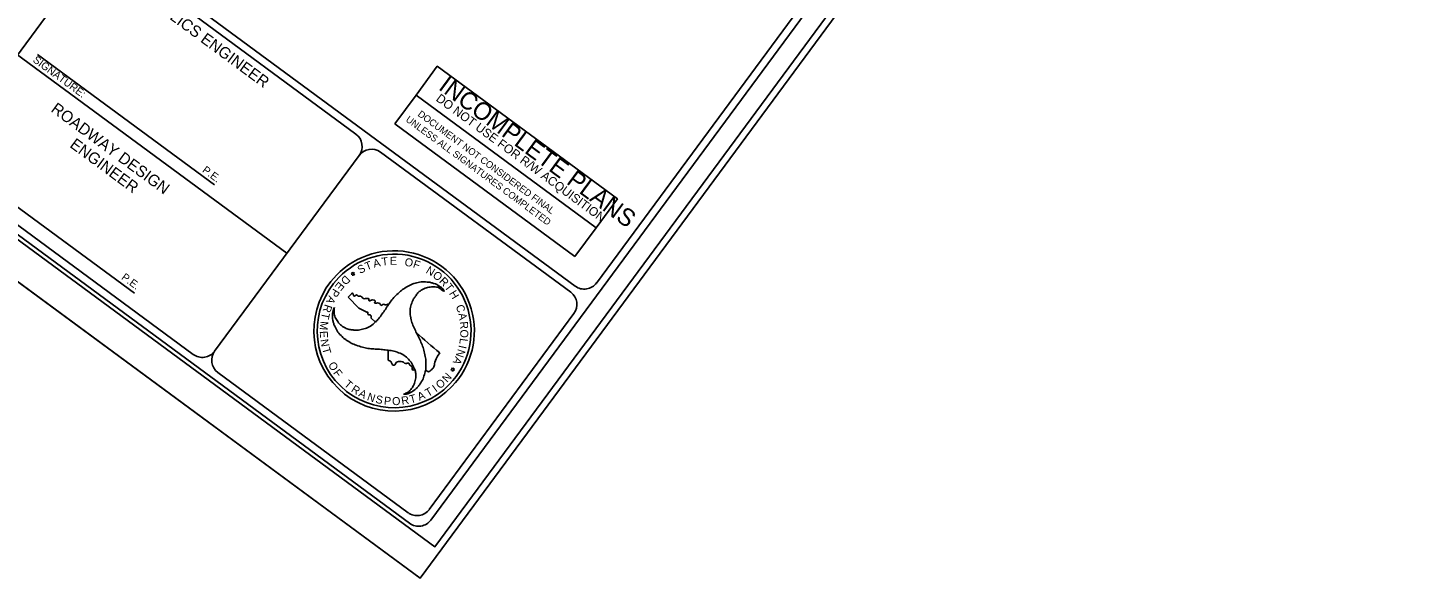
# Model space of a CAD drawing. Extents: x 945666 to 965748, y 644452 to 663300.
# Drawn here: x 956642 to 965748, y 644452 to 648072 of the extents above; entities that cross this region are included whole.
import ezdxf

# ---------------------------------------------------------------- set-up
doc = ezdxf.new("R2010")
doc.units = 0
for name, color, linetype in [('Sheet Cutting Line CELL', 7, 'Continuous'), ('Sheet Plot Border Inside CELL', 7, 'Continuous'), ('Sheet Plot Border Outside CELL', 7, 'Continuous'), ('Sheet Sticker Exception Certification CELL', 7, 'Continuous'), ('Sheet Sticker Incomplete CELL', 7, 'Continuous'), ('Sheet Title CELL', 7, 'Continuous')]:
    doc.layers.add(name, color=color, linetype=linetype)

# ---------------------------------------------------------------- blocks, each defined once
blk = doc.blocks.new('STICKER INCOMPLETE PLANS')
at = {"layer": 'Sheet Sticker Incomplete CELL'}
blk.add_lwpolyline([(0, -0.47), (0, 0), (2.94, 0), (2.94, -0.47)], close=True, dxfattribs=at)
for s, height, p in [('INCOMPLETE PLANS', 0.2304, (0.179, -0.236)), ('DO NOT USE FOR R/W ACQUISITION', 0.1152, (0.244, -0.375))]:
    blk.add_text(s, height=height, dxfattribs=at).set_placement(p)

msp = doc.modelspace()

# ---------------------------------------------------------------- linework, layer by layer
at = {"layer": 'Sheet Cutting Line CELL'}
msp.add_line((945666.1, 654447.6), (959218.9, 644452.2), dxfattribs=at)
at = {"layer": 'Sheet Plot Border Inside CELL'}
msp.add_lwpolyline([(945903.9, 654551), (959315.9, 644659.5), (965578.4, 653150.9), (952166.4, 663042.4)], close=True, dxfattribs=at)
at = {"layer": 'Sheet Plot Border Outside CELL'}
msp.add_lwpolyline([(965747.9, 653304.9), (952195, 663300.2), (945666.1, 654447.6), (959218.9, 644452.2)], close=True, dxfattribs=at)
at = {"layer": 'Sheet Sticker Exception Certification CELL'}
for p, q in [((959052.4, 647440.2), (959191.9, 647629.3)), ((959191.9, 647629.3), (960374.9, 646756.8)), ((960235.4, 646567.7), (959052.4, 647440.2)), ((960374.9, 646756.7), (960235.4, 646567.6))]:
    msp.add_line(p, q, dxfattribs=at)
at = {"layer": 'Sheet Title CELL'}
for p, q in [((948809.3, 654800.8), (960237.5, 646372.5)), ((956100.2, 647249.1), (957049.9, 648536.8)), ((957189.8, 648558), (958797.6, 647372.3)), ((956568.1, 647898.6), (958344, 646588.8)), ((956707.1, 647895.2), (957868.1, 647039)), ((958958.5, 647253.6), (960207.8, 646332.2)), ((956203.7, 647166.2), (957342.4, 646326.2)), ((957869, 645944.8), (958818.7, 647232.5)), ((958765.6, 646451.1), (958773.6, 646455.6)), ((958774.5, 646450.2), (958765.6, 646451.1)), ((958773.6, 646455.6), (958772.1, 646464.6)), ((958772.1, 646464.6), (958778.7, 646458.2)), ((958776.1, 646441), (958774.5, 646450.2)), ((958780.1, 646449.3), (958776.1, 646441)), ((958778.7, 646458.2), (958786.4, 646462.5)), ((958789.3, 646448), (958780.1, 646449.3)), ((958786.4, 646462.5), (958782.8, 646454.3)), ((958782.8, 646454.3), (958789.3, 646448)), ((959378.3, 646340.1), (959376.9, 646339.9)), ((959378.3, 646340.1), (959376.9, 646339.9)), ((958746.4, 646300.7), (958769.2, 646322.8)), ((958815.7, 646228.6), (958746.4, 646300.7)), ((958868.7, 646200.9), (958815.7, 646228.6)), ((958925.5, 646136.3), (958895.8, 646165.6)), ((959194, 646068), (959194, 646068)), ((959008.3, 645886.3), (959009.8, 645951.5)), ((959009.8, 645951.5), (959009.8, 645951.5)), ((959429.4, 645826.9), (959421.4, 645822.5)), ((959421.4, 645822.5), (959430.1, 645821.4)), ((959434.2, 645829.6), (959427.7, 645835.9)), ((959427.7, 645835.9), (959429.4, 645826.9)), ((959430.1, 645821.4), (959431.7, 645812.5)), ((959431.7, 645812.5), (959435.9, 645820.6)), ((959442.1, 645833.8), (959434.2, 645829.6)), ((959435.9, 645820.6), (959445.1, 645819.6)), ((959438.5, 645825.5), (959442.1, 645833.8)), ((959445.1, 645819.6), (959438.5, 645825.5)), ((959427.4, 645712.4), (959427.4, 645712.4))]:
    msp.add_line(p, q, dxfattribs=at)
for points in [[(947238.9, 653598.1), (959149.9, 644813.6)], [(959289.8, 644834.8), (965403.3, 653124.1)], [(960377.3, 646393.5), (965333.4, 653113.7)], [(956121.4, 647109.4), (957729.2, 645923.6)], [(959279.3, 644904.7), (960228.9, 646192.4)], [(957890.2, 645804.9), (959139.4, 644883.6)]]:
    msp.add_lwpolyline(points, dxfattribs=at)
for centre, radius, start, end in [((958738.2, 647291.8), 100, 323.59084, 53.59084), ((958899.2, 647173.1), 100, 53.59084, 143.59084), ((959048.1, 646078.4), 527.2, 316.01198, 136.01198), ((959048.1, 646078.4), 505.2, 316.01198, 136.01198), ((959048.1, 646078.4), 527.2, 136.01198, 316.01198), ((959048.1, 646078.4), 505.2, 136.01198, 316.01198), ((960297.1, 646453.3), 100, 233.59084, 323.59084), ((961085, 648105), 2779.4, 221.69047, 221.79006), ((960148.8, 646252.1), 100, 323.59084, 53.59084), ((961085, 648105), 2779.4, 227.12952, 231.33553), ((957788.9, 646004.6), 100, 233.59084, 323.59084), ((957949.9, 645885.9), 100, 143.59084, 233.59084), ((959199.1, 644964.4), 100, 233.59084, 323.59084), ((959209.6, 644894.5), 100, 233.59084, 323.59084)]:
    msp.add_arc(centre, radius, start, end, dxfattribs=at)
for points in [[(959376.9, 646339.9), (959370.5, 646350.4), (959344.3, 646373.7), (959310.8, 646390.3), (959307.3, 646391.2), (959288, 646396.8), (959264.7, 646399.8), (959225.3, 646400.2), (959186.5, 646391.5), (959170.3, 646387.3), (959153.5, 646379.2), (959119.3, 646360.6), (959089.9, 646338.9), (959059, 646310.3), (959033.9, 646283.4), (959012.1, 646252), (958990.5, 646220.2), (958968.8, 646189.8), (958946.1, 646158.9), (958920.1, 646131.7), (958917.7, 646129.5), (958885, 646105.3), (958848.9, 646091.2), (958813.3, 646084.5), (958795, 646083.3), (958772.7, 646085.7), (958760, 646086.9), (958734.3, 646094.8), (958702.5, 646113.7), (958678.5, 646139.7), (958661.6, 646167.2), (958654, 646199), (958656, 646232.3)], [(959110.1, 645661.7), (959121.8, 645662.1), (959155.3, 645673), (959186.4, 645693.8), (959189.2, 645696), (959203.5, 645710.3), (959217.9, 645729.1), (959238.2, 645762.8), (959249.6, 645800.9), (959254.4, 645816.9), (959255.7, 645835.8), (959256.7, 645874.6), (959252.7, 645910.8), (959243.2, 645951.7), (959232.2, 645986.9), (959216.2, 646021.8), (959199.4, 646056.2), (959184.2, 646089.9), (959168.4, 646125.5), (959158, 646161.4), (959157.5, 646164.7), (959152.6, 646205.5), (959158.7, 646243.7), (959170.3, 646277.8), (959178.8, 646293.8), (959192.1, 646312), (959199.3, 646322.9), (959219.1, 646340.7), (959251.6, 646359), (959285.7, 646366.7), (959317.9, 646367.5), (959349.4, 646358), (959376.9, 646339.9), (959378.3, 646340.1)], [(958769.2, 646322.8), (958770.5, 646325.7), (958776.7, 646324.5), (958783.1, 646309.8), (958793, 646309.2), (958797.2, 646314), (958805.9, 646314.5), (958811.8, 646306), (958826.6, 646308), (958834.1, 646303.6), (958846.9, 646291.2), (958876.8, 646291.9), (958884.1, 646286.6), (958881.8, 646281), (958884.9, 646276.4), (958903.6, 646282.7), (958907, 646282.9), (958923.5, 646276.1), (958924.5, 646270.8), (958920, 646264.3), (958920.6, 646261.6), (958927.2, 646260.6), (958939, 646262.2), (958953.7, 646257.9), (958963.5, 646245.8), (958974.2, 646253), (958995.7, 646249.2), (959003.5, 646251.9), (959009.4, 646256.6)], [(959012.7, 646252.8), (959012.1, 646252), (958990.5, 646220.2), (958968.8, 646189.8), (958946.1, 646158.9), (958925.4, 646136.4)], [(958656, 646232.3), (958650.4, 646221.1), (958643.2, 646186.8), (958645.4, 646149.5), (958646.4, 646146.4), (958651.2, 646126.3), (958660.4, 646104.8), (958679.6, 646070.2), (958706.6, 646041.6), (958718.1, 646029.4), (958734.3, 646018.5), (958767, 645998.7), (958800, 645984), (958840.6, 645971.5), (958876.2, 645963.4), (958914.6, 645960), (958953, 645957.5), (958990.1, 645953.6), (959028.2, 645949.2), (959064.8, 645940.6), (959068.4, 645939.1), (959105.8, 645923), (959135.6, 645899), (959159.1, 645872), (959169.7, 645856.2), (959178, 645835.8), (959184.2, 645824), (959189.8, 645798), (959189.1, 645761.1), (959178.8, 645727.6), (959163.3, 645698.9), (959139.5, 645676.5), (959110.1, 645661.7)], [(958895.8, 646165.6), (958898.2, 646173.9), (958894, 646181.2), (958882.1, 646184.7), (958876.5, 646190.7), (958874.5, 646201.8), (958868.7, 646200.9)], [(959255.5, 645823.6), (959255.7, 645835.8), (959256.7, 645874.6), (959252.7, 645910.8), (959243.2, 645951.7), (959232.2, 645986.9), (959216.2, 646021.8), (959199.4, 646056.2), (959194, 646068)], [(959183.4, 645824.8), (959173.5, 645821.5), (959167.4, 645826.6), (959165.1, 645844.2), (959150.4, 645853.6), (959148, 645862.3), (959144.4, 645866), (959124.7, 645863.4), (959110, 645872.4), (959076.3, 645876.9), (959064.1, 645872.4), (959048, 645852.8), (959039.7, 645853.8), (959034.7, 645860.4), (959027.1, 645876.8), (959008.3, 645886.3)], [(959009.8, 645951.5), (959028.2, 645949.2), (959064.8, 645940.6), (959068.4, 645939.1), (959105.8, 645923), (959135.6, 645899), (959159.1, 645872), (959169.7, 645856.2), (959178, 645835.8), (959183.6, 645824.8)], [(959348.5, 645934.8), (959329.4, 645904.3), (959313.9, 645861.7), (959306.7, 645837.1), (959293, 645823.3), (959273.5, 645809.7), (959255.7, 645823.6)]]:
    msp.add_spline(points, degree=3, dxfattribs=at)

# ---------------------------------------------------------------- block references
at = {"layer": 'Sheet Cutting Line CELL', "xscale": 500, "yscale": 500, "rotation": -36.4091568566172}
msp.add_blockref('STICKER INCOMPLETE PLANS', (959331.4, 647818.4), dxfattribs=at)

# ---------------------------------------------------------------- texts
at = {"layer": 'Sheet Sticker Exception Certification CELL'}
for s, p in [('DOCUMENT NOT CONSIDERED FINAL', (959199.2, 647495.3)), ('UNLESS ALL SIGNATURES COMPLETED', (959120.6, 647459.6))]:
    msp.add_text(s, height=45, rotation=323.59084, dxfattribs=at).set_placement(p)
at = {"layer": 'Sheet Title CELL'}
for s, height, rotation, p in [(' HYDRAULICS ENGINEER', 75, 323.59084, (957206.1, 648399.9)), ('SIGNATURE:', 50, 323.59084, (956671.2, 647851.1)), ('ROADWAY DESIGN', 74.994, 323.59084, (956789.2, 647524.6)), ('ENGINEER', 74.99, 323.59084, (956912.9, 647290.5)), ('P.E.', 50, 323.59084, (957784, 647126.5)), ('T', 52.7, 21.39207, (958868.6, 646475.3)), ('A', 52.7, 14.33976, (958916.7, 646493.4)), ('T', 52.4, 7.28454, (958969.4, 646506.8)), ('E', 52.4, 0.16891, (959020.4, 646513.1)), ('O', 52.6, 348.22953, (959113.5, 646508.8)), ('F', 52.7, 341.08269, (959167.9, 646497.1)), ('P.E.', 50, 323.59084, (957253.3, 646421.9)), ('D', 52.6, 223.86497, (958729.3, 646448.2)), ('S', 52.5, 27.76823, (958824.3, 646452)), ('N', 52.6, 328.99575, (959252.7, 646462.8)), ('O', 52.7, 321.49764, (959296.6, 646436.1)), ('R', 52.6, 314.88771, (959340.1, 646401.5)), ('P', 52.6, 237.68526, (958650.4, 646361.5)), ('E', 52.3, 230.15286, (958686.2, 646406)), ('T', 52.7, 308.23808, (959375.6, 646365.9)), ('H', 52.5, 301.15336, (959407.2, 646325.2)), ('R', 52.6, 251.34647, (958594, 646257.6)), ('A', 52.5, 244.27783, (958620.4, 646314)), ('C', 52.4, 288.81101, (959452.2, 646241.4)), ('T', 52.5, 257.997, (958576, 646202.5)), ('A', 52.5, 281.31398, (959468.9, 646191.6)), ('M', 52.4, 265.23204, (958564.4, 646143.9)), ('E', 52.4, 272.69881, (958559.9, 646077.2)), ('R', 52.5, 274.95004, (959479.6, 646138.7)), ('O', 52.7, 267.83043, (959483.8, 646088.7)), ('N', 52.7, 279.67036, (958563.3, 646020.6)), ('T', 52.5, 286.51236, (958573.8, 645962.2)), ('I', 52.6, 257.60741, (959474, 645987.9)), ('L', 52.4, 261.59676, (959481.6, 646032.7)), ('A', 52.6, 244.47533, (959451.8, 645914)), ('N', 52.5, 251.90731, (959468.2, 645963)), ('O', 52.5, 299.81604, (958612.8, 645857)), ('F', 52.5, 306.98127, (958645.1, 645802.3)), ('N', 52.6, 48.22011, (959396.8, 645735.8)), ('T', 52.4, 319.8905, (958715.2, 645720.8)), ('R', 52.6, 326.84712, (958761.2, 645682.9)), ('T', 52.5, 30.18656, (959270.9, 645643.7)), ('I', 52.7, 35.83646, (959322.1, 645673.7)), ('O', 52.4, 40.97209, (959349.3, 645693.8)), ('A', 52.4, 333.60025, (958810.2, 645651.9)), ('N', 52.4, 340.63188, (958866.3, 645625.1)), ('S', 52.3, 347.84235, (958922.7, 645606.5)), ('P', 52.5, 355.0342, (958979.6, 645594.5)), ('O', 52.7, 1.7262, (959035.7, 645590.1)), ('R', 52.7, 8.9153, (959099.2, 645592.4)), ('T', 52.4, 15.01509, (959156.6, 645602.2)), ('A', 52.7, 23.10213, (959213.9, 645618.6))]:
    msp.add_text(s, height=height, rotation=rotation, dxfattribs=at).set_placement(p)

doc.saveas('drawing.dxf')
